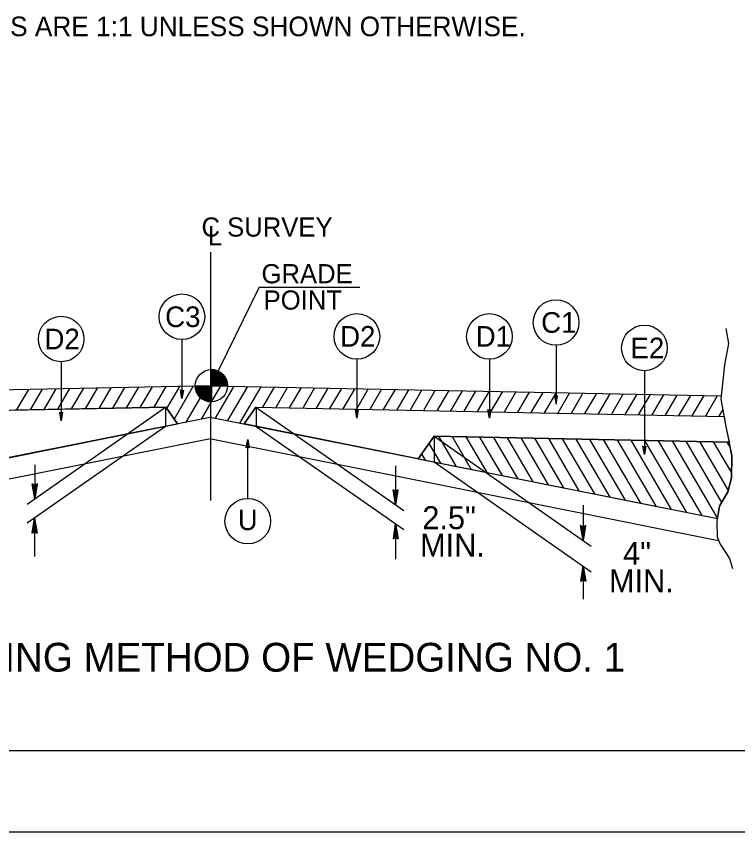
# Model space of a CAD drawing. Extents: x 1553884 to 1554215, y 810431 to 810779.
# Drawn here: x 1554098.35 to 1554128.39, y 810614.43 to 810648.38 of the extents above; entities that cross this region are included whole.
import ezdxf

# ---------------------------------------------------------------- set-up
doc = ezdxf.new("R2010")
doc.units = 0
for name, color, linetype in [('Old_Level_2', 7, 'Continuous'), ('Old_Level_20', 7, 'Continuous'), ('Prop CMT Steel Beam Girder', 7, 'Continuous'), ('Prop Dimension', 7, 'Continuous'), ('Prop Lane Arrow CELL', 7, 'Continuous'), ('Prop Terminator CELL', 7, 'Continuous'), ('Sheet Data Field CELL', 7, 'Continuous'), ('Typical Detail Pavement Repair CELL', 7, 'Continuous'), ('Typical Text Centerline CELL', 7, 'Continuous')]:
    doc.layers.add(name, color=color, linetype=linetype)

msp = doc.modelspace()

# ---------------------------------------------------------------- linework, layer by layer
at = {"layer": 'Old_Level_2'}
msp.add_line((1553906.821, 810617.805), (1554154.321, 810617.805), dxfattribs=at)
at = {"layer": 'Old_Level_20'}
for p, q in [((1554106.446, 810628.216), (1554106.446, 810638.557)), ((1554106.446, 810628.216), (1554106.446, 810635.612)), ((1554105.243, 810634.924), (1554105.243, 810632.471)), ((1554120.821, 810634.686), (1554120.821, 810632.233)), ((1554112.527, 810634.106), (1554112.527, 810631.653)), ((1554118.048, 810634.106), (1554118.048, 810631.653)), ((1554100.214, 810633.998), (1554100.214, 810631.545)), ((1554124.502, 810633.625), (1554124.502, 810630.136)), ((1554106.445, 810633.001), (1554085.194, 810632.576)), ((1554098.849, 810632.849), (1554098.346, 810631.987)), ((1554099.421, 810632.86), (1554098.918, 810631.999)), ((1554099.993, 810632.872), (1554099.49, 810632.01)), ((1554100.566, 810632.883), (1554100.062, 810632.022)), ((1554101.138, 810632.894), (1554100.635, 810632.033)), ((1554101.71, 810632.906), (1554101.207, 810632.045)), ((1554102.282, 810632.917), (1554101.779, 810632.056)), ((1554102.855, 810632.929), (1554102.351, 810632.068)), ((1554103.427, 810632.94), (1554102.923, 810632.079)), ((1554103.999, 810632.952), (1554103.496, 810632.09)), ((1554104.571, 810632.963), (1554104.068, 810632.102)), ((1554105.143, 810632.974), (1554104.605, 810632.054)), ((1554105.716, 810632.986), (1554104.915, 810631.615)), ((1554106.288, 810632.997), (1554105.4, 810631.479)), ((1554106.85, 810632.993), (1554106.041, 810631.607)), ((1554106.448, 810633.001), (1554127.698, 810632.576)), ((1554107.409, 810632.981), (1554106.632, 810631.65)), ((1554107.968, 810632.97), (1554107.138, 810631.549)), ((1554108.527, 810632.959), (1554107.644, 810631.448)), ((1554109.086, 810632.948), (1554108.595, 810632.107)), ((1554109.645, 810632.937), (1554109.154, 810632.095)), ((1554110.204, 810632.925), (1554109.713, 810632.084)), ((1554110.763, 810632.914), (1554110.272, 810632.073)), ((1554111.322, 810632.903), (1554110.831, 810632.062)), ((1554111.881, 810632.892), (1554111.39, 810632.051)), ((1554112.44, 810632.881), (1554111.949, 810632.039)), ((1554112.999, 810632.87), (1554112.507, 810632.029)), ((1554113.558, 810632.859), (1554113.067, 810632.017)), ((1554114.117, 810632.847), (1554113.626, 810632.006)), ((1554114.676, 810632.836), (1554114.185, 810631.995)), ((1554115.235, 810632.825), (1554114.744, 810631.984)), ((1554115.794, 810632.814), (1554115.302, 810631.973)), ((1554116.353, 810632.803), (1554115.862, 810631.961)), ((1554116.912, 810632.791), (1554116.421, 810631.95)), ((1554117.471, 810632.78), (1554116.98, 810631.939)), ((1554118.03, 810632.769), (1554117.539, 810631.928)), ((1554118.589, 810632.758), (1554118.098, 810631.917)), ((1554119.148, 810632.747), (1554118.656, 810631.905)), ((1554119.707, 810632.736), (1554119.216, 810631.894)), ((1554120.266, 810632.724), (1554119.774, 810631.883)), ((1554120.825, 810632.713), (1554120.333, 810631.872)), ((1554121.384, 810632.702), (1554120.893, 810631.861)), ((1554121.943, 810632.691), (1554121.452, 810631.849)), ((1554122.502, 810632.68), (1554122.011, 810631.839)), ((1554123.061, 810632.669), (1554122.569, 810631.827)), ((1554123.62, 810632.657), (1554123.128, 810631.816)), ((1554124.179, 810632.646), (1554123.687, 810631.805)), ((1554124.738, 810632.635), (1554124.247, 810631.794)), ((1554125.297, 810632.624), (1554124.805, 810631.783)), ((1554125.856, 810632.613), (1554125.364, 810631.771)), ((1554126.415, 810632.601), (1554125.923, 810631.76)), ((1554126.974, 810632.59), (1554126.482, 810631.749)), ((1554127.533, 810632.579), (1554127.041, 810631.738)), ((1554104.581, 810632.112), (1554085.073, 810631.722)), ((1554104.557, 810632.096), (1554098.796, 810628.062)), ((1554104.553, 810632.104), (1554104.553, 810631.309)), ((1554104.581, 810632.089), (1554105.059, 810631.41)), ((1554108.326, 810632.112), (1554107.832, 810631.41)), ((1554108.294, 810632.096), (1554108.325, 810632.095)), ((1554108.326, 810632.112), (1554127.819, 810631.722)), ((1554108.326, 810632.112), (1554114.477, 810627.804)), ((1554108.338, 810632.104), (1554108.338, 810631.309)), ((1554106.477, 810631.694), (1554085.354, 810627.468)), ((1554106.414, 810631.694), (1554127.538, 810627.468)), ((1554127.766, 810632.01), (1554127.6, 810631.727)), ((1554104.553, 810631.309), (1554098.796, 810627.278)), ((1554108.338, 810631.309), (1554114.477, 810627.012)), ((1554106.437, 810630.785), (1554085.346, 810626.566)), ((1554106.454, 810630.785), (1554127.593, 810626.556)), ((1554107.983, 810628.31), (1554107.983, 810630.763)), ((1554115.076, 810629.962), (1554115.742, 810630.898)), ((1554115.742, 810630.898), (1554128.026, 810630.652)), ((1554115.742, 810630.898), (1554122.28, 810626.319)), ((1554115.742, 810630.898), (1554115.742, 810629.828)), ((1554115.924, 810630.894), (1554116.653, 810629.646)), ((1554116.496, 810630.883), (1554117.293, 810629.518)), ((1554117.068, 810630.871), (1554117.934, 810629.39)), ((1554117.64, 810630.86), (1554118.574, 810629.262)), ((1554118.213, 810630.849), (1554119.215, 810629.133)), ((1554118.785, 810630.837), (1554119.855, 810629.006)), ((1554119.357, 810630.826), (1554120.495, 810628.877)), ((1554119.929, 810630.814), (1554121.135, 810628.749)), ((1554120.501, 810630.803), (1554121.775, 810628.621)), ((1554121.073, 810630.791), (1554122.416, 810628.493)), ((1554121.646, 810630.78), (1554123.056, 810628.365)), ((1554122.218, 810630.768), (1554123.696, 810628.237)), ((1554122.79, 810630.757), (1554124.337, 810628.109)), ((1554123.362, 810630.745), (1554124.977, 810627.981)), ((1554123.935, 810630.734), (1554125.618, 810627.853)), ((1554124.507, 810630.723), (1554126.258, 810627.725)), ((1554125.079, 810630.711), (1554126.898, 810627.597)), ((1554125.651, 810630.7), (1554127.539, 810627.468)), ((1554126.223, 810630.688), (1554127.714, 810628.136)), ((1554126.795, 810630.677), (1554127.986, 810628.639)), ((1554115.53, 810630.6), (1554116.013, 810629.774)), ((1554127.367, 810630.665), (1554128.125, 810629.369)), ((1554127.94, 810630.654), (1554128.07, 810630.431)), ((1554115.22, 810630.164), (1554115.373, 810629.902)), ((1554099.115, 810629.71), (1554099.115, 810628.286)), ((1554114.142, 810629.671), (1554114.142, 810628.038)), ((1554115.074, 810629.962), (1554127.539, 810627.469)), ((1554115.742, 810629.828), (1554122.28, 810625.249)), ((1554099.115, 810628.286), (1554099.004, 810628.91)), ((1554099.115, 810628.829), (1554099.004, 810628.91)), ((1554099.115, 810628.286), (1554099.02, 810628.898)), ((1554099.036, 810628.886), (1554099.115, 810628.286)), ((1554099.115, 810628.286), (1554099.051, 810628.876)), ((1554099.068, 810628.864), (1554099.115, 810628.286)), ((1554099.115, 810628.286), (1554099.083, 810628.852)), ((1554099.099, 810628.84), (1554099.115, 810628.286)), ((1554099.115, 810628.286), (1554099.225, 810628.91)), ((1554099.225, 810628.91), (1554099.115, 810628.829)), ((1554099.209, 810628.898), (1554099.115, 810628.286)), ((1554099.115, 810628.286), (1554099.193, 810628.886)), ((1554099.177, 810628.876), (1554099.115, 810628.286)), ((1554099.115, 810628.286), (1554099.162, 810628.864)), ((1554099.146, 810628.852), (1554099.115, 810628.286)), ((1554099.115, 810628.286), (1554099.13, 810628.84)), ((1554099.115, 810628.829), (1554099.115, 810628.286)), ((1554114.142, 810628.038), (1554114.033, 810628.663)), ((1554114.142, 810628.582), (1554114.033, 810628.663)), ((1554114.142, 810628.038), (1554114.049, 810628.652)), ((1554114.064, 810628.64), (1554114.142, 810628.038)), ((1554114.142, 810628.038), (1554114.253, 810628.663)), ((1554114.253, 810628.663), (1554114.142, 810628.582)), ((1554114.236, 810628.652), (1554114.142, 810628.038)), ((1554114.142, 810628.038), (1554114.22, 810628.64)), ((1554114.142, 810628.038), (1554114.08, 810628.628)), ((1554114.095, 810628.617), (1554114.142, 810628.038)), ((1554114.142, 810628.038), (1554114.111, 810628.606)), ((1554114.127, 810628.594), (1554114.142, 810628.038)), ((1554114.205, 810628.628), (1554114.142, 810628.038)), ((1554114.142, 810628.038), (1554114.189, 810628.617)), ((1554114.174, 810628.606), (1554114.142, 810628.038)), ((1554114.142, 810628.038), (1554114.158, 810628.594)), ((1554114.142, 810628.582), (1554114.142, 810628.038)), ((1554121.948, 810628.028), (1554121.948, 810626.552)), ((1554099.097, 810627.489), (1554098.987, 810626.864)), ((1554099.002, 810626.876), (1554099.097, 810627.489)), ((1554099.097, 810627.489), (1554099.018, 810626.887)), ((1554099.034, 810626.899), (1554099.097, 810627.489)), ((1554099.097, 810627.489), (1554099.05, 810626.911)), ((1554099.066, 810626.922), (1554099.097, 810627.489)), ((1554099.097, 810627.489), (1554099.082, 810626.933)), ((1554099.097, 810627.489), (1554099.097, 810625.884)), ((1554099.097, 810627.489), (1554099.207, 810626.864)), ((1554099.097, 810626.945), (1554099.097, 810627.489)), ((1554099.113, 810626.933), (1554099.097, 810627.489)), ((1554099.097, 810627.489), (1554099.128, 810626.922)), ((1554099.144, 810626.911), (1554099.097, 810627.489)), ((1554099.097, 810627.489), (1554099.16, 810626.899)), ((1554099.175, 810626.887), (1554099.097, 810627.489)), ((1554099.097, 810627.489), (1554099.192, 810626.876)), ((1554098.987, 810626.864), (1554099.097, 810626.945)), ((1554099.097, 810626.945), (1554099.207, 810626.864)), ((1554114.142, 810627.246), (1554114.033, 810626.621)), ((1554114.049, 810626.633), (1554114.142, 810627.246)), ((1554114.142, 810627.246), (1554114.064, 810626.645)), ((1554114.08, 810626.656), (1554114.142, 810627.246)), ((1554114.142, 810627.246), (1554114.095, 810626.668)), ((1554114.111, 810626.679), (1554114.142, 810627.246)), ((1554114.142, 810627.246), (1554114.127, 810626.691)), ((1554114.142, 810627.246), (1554114.142, 810625.785)), ((1554114.142, 810627.246), (1554114.253, 810626.621)), ((1554114.142, 810626.702), (1554114.142, 810627.246)), ((1554114.158, 810626.691), (1554114.142, 810627.246)), ((1554114.142, 810627.246), (1554114.174, 810626.679)), ((1554114.189, 810626.668), (1554114.142, 810627.246)), ((1554114.142, 810627.246), (1554114.205, 810626.656)), ((1554114.22, 810626.645), (1554114.142, 810627.246)), ((1554114.142, 810627.246), (1554114.236, 810626.633)), ((1554121.948, 810626.552), (1554121.838, 810627.176)), ((1554121.948, 810627.095), (1554121.838, 810627.176)), ((1554121.948, 810626.552), (1554121.853, 810627.164)), ((1554121.869, 810627.153), (1554121.948, 810626.552)), ((1554121.948, 810626.552), (1554121.884, 810627.142)), ((1554121.9, 810627.13), (1554121.948, 810626.552)), ((1554121.948, 810626.552), (1554121.916, 810627.118)), ((1554121.931, 810627.106), (1554121.948, 810626.552)), ((1554121.948, 810626.552), (1554122.058, 810627.176)), ((1554122.058, 810627.176), (1554121.948, 810627.095)), ((1554122.042, 810627.164), (1554121.948, 810626.552)), ((1554121.948, 810626.552), (1554122.026, 810627.153)), ((1554122.011, 810627.142), (1554121.948, 810626.552)), ((1554121.948, 810626.552), (1554121.995, 810627.13)), ((1554121.979, 810627.118), (1554121.948, 810626.552)), ((1554121.948, 810626.552), (1554121.964, 810627.106)), ((1554121.948, 810627.095), (1554121.948, 810626.552)), ((1554114.033, 810626.621), (1554114.142, 810626.702)), ((1554114.142, 810626.702), (1554114.253, 810626.621)), ((1554121.948, 810625.481), (1554121.838, 810624.856)), ((1554121.853, 810624.868), (1554121.948, 810625.481)), ((1554121.948, 810625.481), (1554121.869, 810624.88)), ((1554121.884, 810624.892), (1554121.948, 810625.481)), ((1554121.948, 810625.481), (1554121.9, 810624.903)), ((1554121.916, 810624.915), (1554121.948, 810625.481)), ((1554121.948, 810625.481), (1554121.931, 810624.926)), ((1554121.948, 810625.481), (1554121.948, 810624.109)), ((1554121.948, 810625.481), (1554122.058, 810624.856)), ((1554121.948, 810624.938), (1554121.948, 810625.481)), ((1554121.964, 810624.926), (1554121.948, 810625.481)), ((1554121.948, 810625.481), (1554121.979, 810624.915)), ((1554121.995, 810624.903), (1554121.948, 810625.481)), ((1554121.948, 810625.481), (1554122.011, 810624.892)), ((1554122.026, 810624.88), (1554121.948, 810625.481)), ((1554121.948, 810625.481), (1554122.042, 810624.868)), ((1554121.838, 810624.856), (1554121.948, 810624.938)), ((1554121.948, 810624.938), (1554122.058, 810624.856))]:
    msp.add_line(p, q, dxfattribs=at)
for points in [[(1554127.894, 810635.381), (1554128.007, 810634.758), (1554127.838, 810633.873), (1554127.687, 810632.44), (1554127.894, 810631.309), (1554128.139, 810630.084), (1554128.121, 810629.16), (1554127.969, 810628.576), (1554127.63, 810627.991), (1554127.518, 810627.35), (1554127.536, 810626.71), (1554127.649, 810626.408), (1554128.044, 810625.804), (1554128.176, 810625.389)], [(1554127.538, 810627.468), (1554127.63, 810627.991), (1554127.969, 810628.576), (1554128.121, 810629.16), (1554128.139, 810630.084), (1554128.026, 810630.652)]]:
    msp.add_lwpolyline(points, dxfattribs=at)
for centre in [(1554105.244, 810635.873), (1554120.82, 810635.635), (1554100.215, 810634.947), (1554112.528, 810635.055), (1554118.048, 810635.055), (1554124.502, 810634.574), (1554107.984, 810627.362)]:
    msp.add_circle(centre, 0.949, dxfattribs=at)
at = {"layer": 'Prop CMT Steel Beam Girder'}
for points in [[(1554105.303, 810632.822), (1554105.243, 810632.471), (1554105.18, 810632.824), (1554105.243, 810632.779)], [(1554120.76, 810632.585), (1554120.821, 810632.233), (1554120.883, 810632.587), (1554120.821, 810632.542)], [(1554100.275, 810631.896), (1554100.214, 810631.545), (1554100.152, 810631.899), (1554100.214, 810631.853)], [(1554112.587, 810632.005), (1554112.527, 810631.653), (1554112.464, 810632.007), (1554112.527, 810631.962)], [(1554118.109, 810632.005), (1554118.048, 810631.653), (1554117.986, 810632.007), (1554118.048, 810631.962)], [(1554107.922, 810630.412), (1554107.983, 810630.763), (1554108.045, 810630.41), (1554107.983, 810630.455)], [(1554124.563, 810630.488), (1554124.502, 810630.136), (1554124.44, 810630.49), (1554124.502, 810630.445)]]:
    msp.add_lwpolyline(points, close=True, dxfattribs=at)
at = {"layer": 'Prop Lane Arrow CELL'}
msp.add_line((1553901.353, 810614.43), (1554156.35, 810614.43), dxfattribs=at)
at = {"layer": 'Prop Terminator CELL'}
for points in [[(1554104.581, 810632.089), (1554085.073, 810631.722), (1554084.997, 810631.309), (1554084.866, 810630.652), (1554097.149, 810630.898), (1554097.815, 810629.961), (1554105.059, 810631.41)], [(1554127.819, 810631.722), (1554127.894, 810631.309), (1554128.026, 810630.652), (1554115.742, 810630.898), (1554115.076, 810629.962), (1554107.832, 810631.41), (1554108.326, 810632.112)]]:
    msp.add_lwpolyline(points, close=True, dxfattribs=at)
at = {"layer": 'Sheet Data Field CELL'}
for p, q in [((1554106.469, 810633.001), (1554106.469, 810633.672)), ((1554105.797, 810633.001), (1554106.469, 810633.001)), ((1554106.467, 810632.329), (1554106.469, 810633.001)), ((1554106.469, 810633.001), (1554106.467, 810632.329)), ((1554107.14, 810633.001), (1554106.469, 810633.001))]:
    msp.add_line(p, q, dxfattribs=at)
for points in [[(1554106.475, 810633.672), (1554106.475, 810633.672), (1554106.475, 810633.001)], [(1554106.488, 810633.672), (1554106.488, 810633.001)], [(1554106.502, 810633.671), (1554106.502, 810633.001)], [(1554106.515, 810633.671), (1554106.515, 810633.001)], [(1554106.528, 810633.669), (1554106.528, 810633.001)], [(1554106.542, 810633.668), (1554106.542, 810633.001)], [(1554106.555, 810633.666), (1554106.555, 810633.001)], [(1554106.569, 810633.665), (1554106.569, 810633.001)], [(1554106.582, 810633.663), (1554106.582, 810633.001)], [(1554106.596, 810633.66), (1554106.596, 810633.001)], [(1554106.609, 810633.657), (1554106.609, 810633.001)], [(1554106.622, 810633.654), (1554106.622, 810633.001)], [(1554106.636, 810633.651), (1554106.636, 810633.001)], [(1554106.649, 810633.647), (1554106.649, 810633.001)], [(1554106.663, 810633.644), (1554106.663, 810633.001)], [(1554106.676, 810633.639), (1554106.676, 810633.001)], [(1554106.689, 810633.635), (1554106.689, 810633.001)], [(1554106.703, 810633.63), (1554106.703, 810633.001)], [(1554106.716, 810633.624), (1554106.716, 810633.001)], [(1554106.73, 810633.618), (1554106.73, 810633.001)], [(1554106.743, 810633.612), (1554106.743, 810633.001)], [(1554106.757, 810633.606), (1554106.757, 810633.001)], [(1554106.77, 810633.6), (1554106.77, 810633.001)], [(1554106.783, 810633.593), (1554106.783, 810633.001)], [(1554106.797, 810633.586), (1554106.797, 810633.001)], [(1554106.81, 810633.578), (1554106.81, 810633.001)], [(1554106.824, 810633.571), (1554106.824, 810633.001)], [(1554106.837, 810633.562), (1554106.837, 810633.001)], [(1554106.851, 810633.553), (1554106.851, 810633.001)], [(1554106.864, 810633.542), (1554106.864, 810633.001)], [(1554106.877, 810633.533), (1554106.877, 810633.001)], [(1554106.891, 810633.523), (1554106.891, 810633.001)], [(1554106.904, 810633.511), (1554106.904, 810633.001)], [(1554106.918, 810633.499), (1554106.918, 810633.001)], [(1554106.931, 810633.487), (1554106.931, 810633.001)], [(1554106.945, 810633.474), (1554106.945, 810633.001)], [(1554106.958, 810633.46), (1554106.958, 810633.001)], [(1554106.971, 810633.445), (1554106.971, 810633.001)], [(1554106.985, 810633.429), (1554106.985, 810633.001)], [(1554106.998, 810633.412), (1554106.998, 810633.001)], [(1554107.012, 810633.395), (1554107.012, 810633.001)], [(1554107.025, 810633.375), (1554107.025, 810633.001)], [(1554107.039, 810633.354), (1554107.039, 810633.001)], [(1554107.052, 810633.332), (1554107.052, 810633.001)], [(1554107.065, 810633.308), (1554107.065, 810633.001)], [(1554107.079, 810633.28), (1554107.079, 810633.001)], [(1554107.092, 810633.248), (1554107.092, 810633.001)], [(1554107.106, 810633.211), (1554107.106, 810633.001)], [(1554107.119, 810633.165), (1554107.119, 810633.001)], [(1554107.133, 810633.096), (1554107.133, 810633.001)], [(1554105.8, 810633.001), (1554105.8, 810632.928)], [(1554105.814, 810633.001), (1554105.814, 810632.848)], [(1554105.827, 810633.001), (1554105.827, 810632.801)], [(1554105.841, 810633.001), (1554105.841, 810632.76)], [(1554105.854, 810633.001), (1554105.854, 810632.729)], [(1554105.867, 810633.001), (1554105.867, 810632.701)], [(1554105.881, 810633.001), (1554105.881, 810632.675)], [(1554105.894, 810633.001), (1554105.894, 810632.652)], [(1554105.908, 810633.001), (1554105.908, 810632.631)], [(1554105.921, 810633.001), (1554105.921, 810632.611)], [(1554105.935, 810633.001), (1554105.935, 810632.593)], [(1554105.948, 810633.001), (1554105.948, 810632.577)], [(1554105.961, 810633.001), (1554105.961, 810632.561)], [(1554105.975, 810633.001), (1554105.975, 810632.546)], [(1554105.988, 810633.001), (1554105.988, 810632.531)], [(1554106.002, 810633.001), (1554106.002, 810632.517)], [(1554106.015, 810633.001), (1554106.015, 810632.505)], [(1554106.029, 810633.001), (1554106.029, 810632.493)], [(1554106.042, 810633.001), (1554106.042, 810632.482)], [(1554106.055, 810633.001), (1554106.055, 810632.471)], [(1554106.069, 810633.001), (1554106.069, 810632.461)], [(1554106.082, 810633.001), (1554106.082, 810632.452)], [(1554106.096, 810633.001), (1554106.096, 810632.443)], [(1554106.109, 810633.001), (1554106.109, 810632.434)], [(1554106.123, 810633.001), (1554106.123, 810632.425)], [(1554106.136, 810633.001), (1554106.136, 810632.417)], [(1554106.149, 810633.001), (1554106.149, 810632.41)], [(1554106.163, 810633.001), (1554106.163, 810632.402)], [(1554106.176, 810633.001), (1554106.176, 810632.396)], [(1554106.19, 810633.001), (1554106.19, 810632.39)], [(1554106.203, 810633.001), (1554106.203, 810632.384)], [(1554106.217, 810633.001), (1554106.217, 810632.379)], [(1554106.23, 810633.001), (1554106.23, 810632.373)], [(1554106.243, 810633.001), (1554106.243, 810632.368)], [(1554106.257, 810633.001), (1554106.257, 810632.364)], [(1554106.27, 810633.001), (1554106.27, 810632.359)], [(1554106.284, 810633.001), (1554106.284, 810632.356)], [(1554106.297, 810633.001), (1554106.297, 810632.352)], [(1554106.311, 810633.001), (1554106.311, 810632.349)], [(1554106.324, 810633.001), (1554106.324, 810632.346)], [(1554106.337, 810633.001), (1554106.337, 810632.343)], [(1554106.351, 810633.001), (1554106.351, 810632.34)], [(1554106.364, 810633.001), (1554106.364, 810632.338)], [(1554106.378, 810633.001), (1554106.378, 810632.335)], [(1554106.391, 810633.001), (1554106.391, 810632.334)], [(1554106.405, 810633.001), (1554106.405, 810632.332)], [(1554106.418, 810633.001), (1554106.418, 810632.331)], [(1554106.431, 810633.001), (1554106.431, 810632.331)], [(1554106.445, 810633.001), (1554106.445, 810632.329)], [(1554106.458, 810633.001), (1554106.458, 810632.329), (1554106.458, 810632.329)]]:
    msp.add_lwpolyline(points, dxfattribs=at)
msp.add_circle((1554106.468, 810633.001), 0.671, dxfattribs=at)
for start, end in [(359.9905, 89.9905), (179.9905, 269.9905)]:
    msp.add_arc((1554106.468, 810633.001), 0.671, start, end, dxfattribs=at)
at = {"layer": 'Typical Text Centerline CELL'}
for q in [(1554106.448, 810633.001), (1554112.649, 810637.107)]:
    msp.add_line((1554108.459, 810637.107), q, dxfattribs=at)

# ---------------------------------------------------------------- texts
at = {"layer": 'Old_Level_20'}
for s, height, p in [('C SURVEY ', 0.7987, (1554106.056, 810639.211)), ('L', 0.799, (1554106.32, 810638.849)), ('GRADE', 0.7987, (1554108.555, 810637.267)), ('POINT', 0.7987, (1554108.643, 810636.171)), ('2.5"', 0.9558, (1554115.253, 810627.027)), ('MIN.', 0.9558, (1554115.16, 810625.883)), ('4"', 0.9558, (1554123.612, 810625.543)), ('MIN.', 0.9558, (1554123.026, 810624.398)), ('DETAIL SHOWING METHOD OF WEDGING NO. 1', 1.2, (1554086.788, 810621.094))]:
    msp.add_text(s, height=height, dxfattribs=at).set_placement(p)
at = {"layer": 'Prop Dimension'}
msp.add_text('NOTE: PAVEMENT EDGE SLOPES ARE 1:1 UNLESS SHOWN OTHERWISE.', height=0.81625, dxfattribs=at).set_placement((1554081.105, 810647.557))
at = {"layer": 'Typical Detail Pavement Repair CELL'}
for s, height, p in [('C3', 0.8608, (1554104.543, 810635.443)), ('C1', 0.8608, (1554120.202, 810635.205)), ('D2', 0.8608, (1554111.829, 810634.625)), ('D1', 0.8608, (1554117.475, 810634.625)), ('D2', 0.8608, (1554099.517, 810634.516)), ('E2', 0.8608, (1554123.92, 810634.143)), ('U', 0.85, (1554107.572, 810626.989))]:
    msp.add_text(s, height=height, dxfattribs=at).set_placement(p)

doc.saveas('drawing.dxf')
